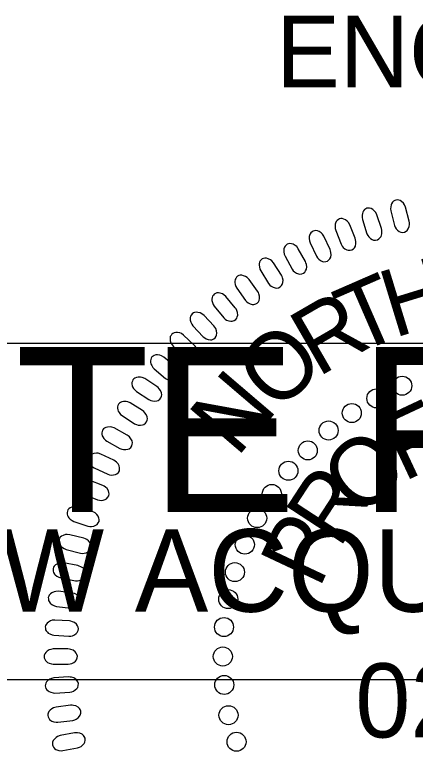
# Model space of a CAD drawing. Extents: x 1487909 to 1489267, y 497866 to 499814.
# Drawn here: x 1489041.55 to 1489044.35, y 498085.53 to 498090.67 of the extents above; entities that cross this region are included whole.
import ezdxf

# ---------------------------------------------------------------- set-up
doc = ezdxf.new("R2010")
doc.units = 0
for name, color, linetype in [('Old_Level_9', 7, 'Continuous'), ('Sheet Sticker Incomplete CELL', 7, 'Continuous'), ('Sheet Typical CELL', 7, 'Continuous')]:
    doc.layers.add(name, color=color, linetype=linetype)

msp = doc.modelspace()

# ---------------------------------------------------------------- linework, layer by layer
at = {"layer": 'Old_Level_9'}
for points in [[(1489044.308, 498089.2251), (1489044.2827, 498089.3237), (1489044.2752, 498089.3406), (1489044.2681, 498089.3508), (1489044.2556, 498089.362), (1489044.2455, 498089.3688), (1489044.2349, 498089.373), (1489044.2256, 498089.3741), (1489044.2162, 498089.3733), (1489044.2076, 498089.3694), (1489044.1986, 498089.3645), (1489044.1914, 498089.3576), (1489044.1851, 498089.3474), (1489044.1819, 498089.3398), (1489044.1795, 498089.3263), (1489044.1785, 498089.3107), (1489044.1799, 498089.2974), (1489044.2052, 498089.1962), (1489044.2105, 498089.183), (1489044.217, 498089.1727), (1489044.2275, 498089.1617), (1489044.2394, 498089.1528), (1489044.2489, 498089.1484), (1489044.2628, 498089.1468), (1489044.2752, 498089.1483), (1489044.2864, 498089.1546), (1489044.2938, 498089.1607), (1489044.3019, 498089.1714), (1489044.308, 498089.1875), (1489044.3097, 498089.2033), (1489044.3095, 498089.2143)], [(1489044.1143, 498089.1736), (1489044.0829, 498089.2704), (1489044.0743, 498089.2868), (1489044.0666, 498089.2964), (1489044.0534, 498089.307), (1489044.0429, 498089.3132), (1489044.0321, 498089.3166), (1489044.0227, 498089.3171), (1489044.0134, 498089.3157), (1489044.005, 498089.3113), (1489043.9964, 498089.3059), (1489043.9897, 498089.2985), (1489043.9839, 498089.2879), (1489043.9813, 498089.2801), (1489043.9798, 498089.2665), (1489043.9797, 498089.2508), (1489043.982, 498089.2376), (1489044.0136, 498089.1383), (1489044.0197, 498089.1255), (1489044.0268, 498089.1156), (1489044.038, 498089.1053), (1489044.0504, 498089.0971), (1489044.0601, 498089.0933), (1489044.0741, 498089.0926), (1489044.0864, 498089.0949), (1489044.0972, 498089.1019), (1489044.1042, 498089.1085), (1489044.1116, 498089.1196), (1489044.1167, 498089.1361), (1489044.1174, 498089.152), (1489044.1165, 498089.163)], [(1489043.9317, 498089.1058), (1489043.8942, 498089.2005), (1489043.8846, 498089.2163), (1489043.8763, 498089.2255), (1489043.8625, 498089.2351), (1489043.8516, 498089.2406), (1489043.8406, 498089.2433), (1489043.8313, 498089.2432), (1489043.822, 498089.2413), (1489043.8139, 498089.2364), (1489043.8056, 498089.2304), (1489043.7994, 498089.2226), (1489043.7943, 498089.2117), (1489043.7922, 498089.2038), (1489043.7915, 498089.1901), (1489043.7924, 498089.1745), (1489043.7955, 498089.1615), (1489043.8333, 498089.0642), (1489043.8402, 498089.0519), (1489043.848, 498089.0425), (1489043.8598, 498089.0328), (1489043.8726, 498089.0255), (1489043.8826, 498089.0223), (1489043.8966, 498089.0225), (1489043.9087, 498089.0255), (1489043.919, 498089.0332), (1489043.9255, 498089.0402), (1489043.9323, 498089.0518), (1489043.9364, 498089.0685), (1489043.9361, 498089.0845), (1489043.9345, 498089.0954)], [(1489043.7559, 498089.0284), (1489043.7126, 498089.1205), (1489043.702, 498089.1356), (1489043.6931, 498089.1443), (1489043.6788, 498089.1532), (1489043.6676, 498089.1579), (1489043.6563, 498089.1599), (1489043.6471, 498089.1592), (1489043.6379, 498089.1568), (1489043.6302, 498089.1513), (1489043.6223, 498089.1449), (1489043.6166, 498089.1367), (1489043.6122, 498089.1255), (1489043.6105, 498089.1174), (1489043.6108, 498089.1038), (1489043.6126, 498089.0882), (1489043.6166, 498089.0754), (1489043.6604, 498088.9808), (1489043.668, 498088.9688), (1489043.6764, 498088.9599), (1489043.6887, 498088.9511), (1489043.7021, 498088.9445), (1489043.7122, 498088.942), (1489043.7261, 498088.9431), (1489043.738, 498088.9468), (1489043.7478, 498088.9551), (1489043.754, 498088.9625), (1489043.76, 498088.9745), (1489043.763, 498088.9914), (1489043.7617, 498089.0073), (1489043.7594, 498089.0181)], [(1489043.583, 498088.9442), (1489043.534, 498089.0335), (1489043.5225, 498089.048), (1489043.5131, 498089.056), (1489043.4982, 498089.0639), (1489043.4867, 498089.068), (1489043.4754, 498089.0693), (1489043.4662, 498089.068), (1489043.4572, 498089.065), (1489043.4499, 498089.0591), (1489043.4423, 498089.0521), (1489043.4371, 498089.0436), (1489043.4335, 498089.0321), (1489043.4324, 498089.0239), (1489043.4334, 498089.0104), (1489043.4362, 498088.9949), (1489043.441, 498088.9824), (1489043.4907, 498088.8907), (1489043.499, 498088.8793), (1489043.5079, 498088.8709), (1489043.5208, 498088.8629), (1489043.5346, 498088.8572), (1489043.5448, 498088.8553), (1489043.5586, 498088.8572), (1489043.5703, 498088.8617), (1489043.5796, 498088.8706), (1489043.5852, 498088.8784), (1489043.5905, 498088.8907), (1489043.5924, 498088.9078), (1489043.5901, 498088.9236), (1489043.5871, 498088.9342)], [(1489043.4156, 498088.8494), (1489043.361, 498088.9354), (1489043.3486, 498088.9492), (1489043.3388, 498088.9566), (1489043.3234, 498088.9636), (1489043.3117, 498088.9669), (1489043.3003, 498088.9675), (1489043.2912, 498088.9656), (1489043.2825, 498088.962), (1489043.2754, 498088.9557), (1489043.2684, 498088.9483), (1489043.2637, 498088.9394), (1489043.2608, 498088.9278), (1489043.2602, 498088.9195), (1489043.2621, 498088.906), (1489043.266, 498088.8908), (1489043.2714, 498088.8786), (1489043.3268, 498088.7902), (1489043.3359, 498088.7793), (1489043.3453, 498088.7715), (1489043.3586, 498088.7643), (1489043.3727, 498088.7595), (1489043.383, 498088.7582), (1489043.3967, 498088.761), (1489043.4081, 498088.7663), (1489043.4168, 498088.7757), (1489043.4219, 498088.7839), (1489043.4264, 498088.7965), (1489043.4272, 498088.8137), (1489043.4239, 498088.8293), (1489043.4203, 498088.8397)], [(1489043.2495, 498088.737), (1489043.1897, 498088.8194), (1489043.1765, 498088.8323), (1489043.1662, 498088.8392), (1489043.1503, 498088.8451), (1489043.1385, 498088.8477), (1489043.1271, 498088.8476), (1489043.1181, 498088.8452), (1489043.1096, 498088.841), (1489043.103, 498088.8342), (1489043.0965, 498088.8264), (1489043.0923, 498088.8173), (1489043.0902, 498088.8055), (1489043.09, 498088.7972), (1489043.0928, 498088.7838), (1489043.0975, 498088.7689), (1489043.1038, 498088.7571), (1489043.1646, 498088.6723), (1489043.1744, 498088.662), (1489043.1842, 498088.6548), (1489043.198, 498088.6485), (1489043.2123, 498088.6446), (1489043.2228, 498088.6439), (1489043.2362, 498088.6476), (1489043.2472, 498088.6535), (1489043.2553, 498088.6635), (1489043.2599, 498088.6719), (1489043.2636, 498088.6848), (1489043.2634, 498088.7021), (1489043.2591, 498088.7174), (1489043.2548, 498088.7276)], [(1489043.0934, 498088.6217), (1489043.0285, 498088.7002), (1489043.0146, 498088.7122), (1489043.0038, 498088.7184), (1489042.9877, 498088.7233), (1489042.9757, 498088.7252), (1489042.9643, 498088.7244), (1489042.9555, 498088.7214), (1489042.9473, 498088.7167), (1489042.9411, 498088.7095), (1489042.9351, 498088.7013), (1489042.9315, 498088.6919), (1489042.9301, 498088.68), (1489042.9305, 498088.6717), (1489042.9341, 498088.6586), (1489042.9397, 498088.644), (1489042.9468, 498088.6325), (1489043.0127, 498088.5518), (1489043.0232, 498088.5421), (1489043.0334, 498088.5356), (1489043.0476, 498088.5301), (1489043.0621, 498088.5271), (1489043.0726, 498088.5271), (1489043.0858, 498088.5316), (1489043.0964, 498088.5383), (1489043.1038, 498088.5487), (1489043.1079, 498088.5574), (1489043.1108, 498088.5705), (1489043.1094, 498088.5877), (1489043.1042, 498088.6027), (1489043.0993, 498088.6126)], [(1489042.945, 498088.494), (1489042.8754, 498088.5682), (1489042.8607, 498088.5794), (1489042.8495, 498088.5849), (1489042.8331, 498088.5888), (1489042.8211, 498088.5899), (1489042.8097, 498088.5884), (1489042.8011, 498088.5848), (1489042.7932, 498088.5797), (1489042.7875, 498088.5721), (1489042.782, 498088.5634), (1489042.779, 498088.5539), (1489042.7784, 498088.5419), (1489042.7793, 498088.5337), (1489042.7837, 498088.5208), (1489042.7903, 498088.5066), (1489042.798, 498088.4957), (1489042.8689, 498088.4192), (1489042.8799, 498088.4102), (1489042.8905, 498088.4043), (1489042.905, 498088.3997), (1489042.9198, 498088.3976), (1489042.9302, 498088.3983), (1489042.9431, 498088.4036), (1489042.9533, 498088.4109), (1489042.96, 498088.4218), (1489042.9636, 498088.4308), (1489042.9656, 498088.444), (1489042.9632, 498088.461), (1489042.957, 498088.4758), (1489042.9515, 498088.4853)], [(1489042.8071, 498088.3604), (1489042.7329, 498088.4301), (1489042.7175, 498088.4403), (1489042.7061, 498088.4451), (1489042.6894, 498088.448), (1489042.6773, 498088.4483), (1489042.6661, 498088.4461), (1489042.6577, 498088.442), (1489042.6501, 498088.4364), (1489042.645, 498088.4285), (1489042.64, 498088.4195), (1489042.6377, 498088.4098), (1489042.6377, 498088.3978), (1489042.6392, 498088.3896), (1489042.6444, 498088.377), (1489042.6518, 498088.3633), (1489042.6602, 498088.3528), (1489042.7358, 498088.2809), (1489042.7473, 498088.2727), (1489042.7583, 498088.2674), (1489042.7731, 498088.2638), (1489042.7879, 498088.2627), (1489042.7982, 498088.264), (1489042.8108, 498088.2701), (1489042.8205, 498088.278), (1489042.8265, 498088.2893), (1489042.8295, 498088.2984), (1489042.8307, 498088.3118), (1489042.8272, 498088.3287), (1489042.8202, 498088.343), (1489042.8141, 498088.3521)], [(1489042.6732, 498088.2121), (1489042.5948, 498088.277), (1489042.5787, 498088.2862), (1489042.5671, 498088.2903), (1489042.5503, 498088.2921), (1489042.5381, 498088.2917), (1489042.5271, 498088.2887), (1489042.519, 498088.2842), (1489042.5118, 498088.278), (1489042.5071, 498088.2698), (1489042.5027, 498088.2606), (1489042.501, 498088.2508), (1489042.5018, 498088.2388), (1489042.5038, 498088.2307), (1489042.5098, 498088.2185), (1489042.5181, 498088.2051), (1489042.5271, 498088.1953), (1489042.607, 498088.1283), (1489042.6191, 498088.1208), (1489042.6304, 498088.1163), (1489042.6453, 498088.1135), (1489042.6601, 498088.1133), (1489042.6704, 498088.1154), (1489042.6826, 498088.1222), (1489042.6917, 498088.1307), (1489042.6971, 498088.1424), (1489042.6994, 498088.1517), (1489042.6998, 498088.1651), (1489042.6953, 498088.1817), (1489042.6874, 498088.1955), (1489042.6806, 498088.2043)], [(1489042.5466, 498088.0708), (1489042.4611, 498088.1261), (1489042.4441, 498088.1333), (1489042.4321, 498088.136), (1489042.4152, 498088.1358), (1489042.4032, 498088.134), (1489042.3926, 498088.1298), (1489042.3851, 498088.1243), (1489042.3786, 498088.1173), (1489042.3749, 498088.1086), (1489042.3717, 498088.0989), (1489042.3711, 498088.089), (1489042.3733, 498088.0772), (1489042.3762, 498088.0694), (1489042.3836, 498088.058), (1489042.3934, 498088.0457), (1489042.4035, 498088.037), (1489042.4908, 498087.9798), (1489042.5036, 498087.9737), (1489042.5154, 498087.9706), (1489042.5306, 498087.9697), (1489042.5453, 498087.9712), (1489042.5553, 498087.9744), (1489042.5665, 498087.9826), (1489042.5746, 498087.9921), (1489042.5786, 498088.0044), (1489042.5798, 498088.0139), (1489042.5786, 498088.0273), (1489042.5722, 498088.0432), (1489042.5627, 498088.056), (1489042.555, 498088.0639)], [(1489042.4458, 498087.9029), (1489042.3599, 498087.9575), (1489042.3429, 498087.9646), (1489042.3308, 498087.9672), (1489042.3139, 498087.9669), (1489042.3019, 498087.965), (1489042.2913, 498087.9607), (1489042.2838, 498087.9551), (1489042.2774, 498087.9481), (1489042.2739, 498087.9394), (1489042.2707, 498087.9297), (1489042.2702, 498087.9197), (1489042.2725, 498087.9079), (1489042.2754, 498087.9002), (1489042.2829, 498087.8888), (1489042.2928, 498087.8766), (1489042.303, 498087.868), (1489042.3907, 498087.8115), (1489042.4036, 498087.8056), (1489042.4154, 498087.8025), (1489042.4305, 498087.8017), (1489042.4453, 498087.8033), (1489042.4552, 498087.8065), (1489042.4664, 498087.8149), (1489042.4745, 498087.8245), (1489042.4783, 498087.8367), (1489042.4795, 498087.8463), (1489042.4782, 498087.8597), (1489042.4716, 498087.8755), (1489042.462, 498087.8882), (1489042.4543, 498087.8961)], [(1489042.3377, 498087.7328), (1489042.2484, 498087.7819), (1489042.231, 498087.788), (1489042.2187, 498087.7898), (1489042.2019, 498087.7884), (1489042.19, 498087.7857), (1489042.1798, 498087.7808), (1489042.1727, 498087.7748), (1489042.1667, 498087.7674), (1489042.1637, 498087.7584), (1489042.1611, 498087.7486), (1489042.1612, 498087.7386), (1489042.1643, 498087.727), (1489042.1677, 498087.7194), (1489042.1759, 498087.7085), (1489042.1866, 498087.697), (1489042.1973, 498087.689), (1489042.2884, 498087.6382), (1489042.3016, 498087.633), (1489042.3135, 498087.6307), (1489042.3287, 498087.6308), (1489042.3434, 498087.6334), (1489042.3531, 498087.6373), (1489042.3637, 498087.6463), (1489042.3711, 498087.6564), (1489042.3742, 498087.6688), (1489042.3748, 498087.6784), (1489042.3726, 498087.6917), (1489042.3651, 498087.7071), (1489042.3547, 498087.7192), (1489042.3465, 498087.7266)], [(1489042.2456, 498087.5566), (1489042.1535, 498087.5999), (1489042.1357, 498087.6049), (1489042.1234, 498087.6059), (1489042.1067, 498087.6035), (1489042.095, 498087.6001), (1489042.0851, 498087.5945), (1489042.0783, 498087.588), (1489042.0729, 498087.5803), (1489042.0704, 498087.5712), (1489042.0685, 498087.5611), (1489042.0692, 498087.5512), (1489042.073, 498087.5398), (1489042.0769, 498087.5325), (1489042.0858, 498087.5221), (1489042.0971, 498087.5113), (1489042.1083, 498087.5039), (1489042.2025, 498087.4589), (1489042.2159, 498087.4547), (1489042.228, 498087.4531), (1489042.2431, 498087.4542), (1489042.2576, 498087.4577), (1489042.267, 498087.4621), (1489042.2771, 498087.4718), (1489042.2839, 498087.4823), (1489042.2861, 498087.495), (1489042.2861, 498087.5046), (1489042.2831, 498087.5177), (1489042.2746, 498087.5327), (1489042.2635, 498087.544), (1489042.2548, 498087.5509)], [(1489042.1677, 498087.3807), (1489042.073, 498087.4182), (1489042.0549, 498087.422), (1489042.0426, 498087.4223), (1489042.026, 498087.4188), (1489042.0146, 498087.4147), (1489042.005, 498087.4084), (1489041.9988, 498087.4016), (1489041.9938, 498087.3935), (1489041.9919, 498087.3843), (1489041.9906, 498087.3741), (1489041.9919, 498087.3642), (1489041.9964, 498087.3531), (1489042.0008, 498087.346), (1489042.0103, 498087.3363), (1489042.0223, 498087.3262), (1489042.0339, 498087.3196), (1489042.1306, 498087.2806), (1489042.1444, 498087.2772), (1489042.1566, 498087.2763), (1489042.1716, 498087.2783), (1489042.1858, 498087.2827), (1489042.1949, 498087.2878), (1489042.2044, 498087.2981), (1489042.2105, 498087.309), (1489042.212, 498087.3217), (1489042.2113, 498087.3314), (1489042.2075, 498087.3442), (1489042.1981, 498087.3586), (1489042.1862, 498087.3693), (1489042.1771, 498087.3756)], [(1489042.095, 498087.199), (1489041.9981, 498087.2305), (1489041.9799, 498087.2331), (1489041.9675, 498087.2327), (1489041.9512, 498087.2282), (1489041.94, 498087.2233), (1489041.9309, 498087.2165), (1489041.9251, 498087.2093), (1489041.9206, 498087.2009), (1489041.9193, 498087.1915), (1489041.9186, 498087.1813), (1489041.9206, 498087.1716), (1489041.9258, 498087.1607), (1489041.9306, 498087.1539), (1489041.9407, 498087.1448), (1489041.9533, 498087.1355), (1489041.9653, 498087.1296), (1489042.0643, 498087.0967), (1489042.0783, 498087.0942), (1489042.0905, 498087.0941), (1489042.1053, 498087.0971), (1489042.1192, 498087.1024), (1489042.1281, 498087.108), (1489042.1368, 498087.1188), (1489042.1422, 498087.1301), (1489042.1429, 498087.143), (1489042.1416, 498087.1525), (1489042.1371, 498087.1651), (1489042.1267, 498087.1789), (1489042.1143, 498087.1888), (1489042.1048, 498087.1945)], [(1489042.0365, 498087.0118), (1489041.9379, 498087.0371), (1489041.9195, 498087.0386), (1489041.9071, 498087.0374), (1489041.8912, 498087.0318), (1489041.8804, 498087.0263), (1489041.8716, 498087.019), (1489041.8663, 498087.0113), (1489041.8623, 498087.0027), (1489041.8616, 498086.9934), (1489041.8616, 498086.9831), (1489041.8642, 498086.9734), (1489041.8701, 498086.963), (1489041.8752, 498086.9565), (1489041.8859, 498086.948), (1489041.8991, 498086.9395), (1489041.9114, 498086.9344), (1489042.0123, 498086.9078), (1489042.0264, 498086.9061), (1489042.0386, 498086.9068), (1489042.0532, 498086.9108), (1489042.0667, 498086.9169), (1489042.0752, 498086.923), (1489042.0833, 498086.9344), (1489042.0879, 498086.946), (1489042.0878, 498086.9588), (1489042.086, 498086.9683), (1489042.0806, 498086.9806), (1489042.0695, 498086.9937), (1489042.0564, 498087.0028), (1489042.0466, 498087.0079)], [(1489041.9941, 498086.8212), (1489041.8941, 498086.8403), (1489041.8756, 498086.8407), (1489041.8634, 498086.8387), (1489041.8478, 498086.8321), (1489041.8373, 498086.826), (1489041.8291, 498086.818), (1489041.8242, 498086.8101), (1489041.8208, 498086.8013), (1489041.8208, 498086.7919), (1489041.8213, 498086.7816), (1489041.8245, 498086.7722), (1489041.8311, 498086.7621), (1489041.8366, 498086.756), (1489041.8478, 498086.7481), (1489041.8615, 498086.7405), (1489041.8741, 498086.7362), (1489041.9765, 498086.7159), (1489041.9907, 498086.7152), (1489042.0027, 498086.7167), (1489042.0171, 498086.7215), (1489042.0303, 498086.7284), (1489042.0383, 498086.7351), (1489042.0456, 498086.747), (1489042.0496, 498086.7589), (1489042.0486, 498086.7717), (1489042.0462, 498086.781), (1489042.0401, 498086.7929), (1489042.0281, 498086.8053), (1489042.0145, 498086.8136), (1489042.0044, 498086.818)], [(1489041.9592, 498086.6291), (1489041.8582, 498086.6419), (1489041.8397, 498086.6412), (1489041.8276, 498086.6383), (1489041.8125, 498086.6309), (1489041.8025, 498086.624), (1489041.7947, 498086.6156), (1489041.7904, 498086.6074), (1489041.7875, 498086.5983), (1489041.788, 498086.5889), (1489041.7893, 498086.5787), (1489041.7931, 498086.5695), (1489041.8002, 498086.5599), (1489041.8062, 498086.5541), (1489041.8178, 498086.547), (1489041.8319, 498086.5402), (1489041.8448, 498086.5367), (1489041.9482, 498086.523), (1489041.9624, 498086.5231), (1489041.9744, 498086.5253), (1489041.9884, 498086.531), (1489042.0011, 498086.5388), (1489042.0087, 498086.546), (1489042.0153, 498086.5583), (1489042.0185, 498086.5704), (1489042.0167, 498086.5831), (1489042.0137, 498086.5923), (1489042.0069, 498086.6038), (1489041.9941, 498086.6153), (1489041.98, 498086.6228), (1489041.9697, 498086.6266)], [(1489041.9354, 498086.4346), (1489041.8338, 498086.441), (1489041.8154, 498086.4391), (1489041.8035, 498086.4355), (1489041.7889, 498086.4271), (1489041.7793, 498086.4196), (1489041.7721, 498086.4108), (1489041.7683, 498086.4023), (1489041.766, 498086.3931), (1489041.7671, 498086.3837), (1489041.769, 498086.3736), (1489041.7733, 498086.3647), (1489041.7811, 498086.3555), (1489041.7874, 498086.3501), (1489041.7994, 498086.3437), (1489041.814, 498086.3378), (1489041.8271, 498086.3352), (1489041.9311, 498086.3279), (1489041.9453, 498086.3289), (1489041.9571, 498086.3319), (1489041.9708, 498086.3385), (1489041.9829, 498086.347), (1489041.9901, 498086.3547), (1489041.9958, 498086.3674), (1489041.9982, 498086.3797), (1489041.9957, 498086.3922), (1489041.9921, 498086.4012), (1489041.9846, 498086.4122), (1489041.9712, 498086.423), (1489041.9566, 498086.4296), (1489041.946, 498086.4327)], [(1489041.9246, 498086.2395), (1489041.8228, 498086.2395), (1489041.8046, 498086.2364), (1489041.793, 498086.2321), (1489041.7789, 498086.2228), (1489041.7698, 498086.2147), (1489041.7632, 498086.2054), (1489041.7599, 498086.1967), (1489041.7582, 498086.1874), (1489041.7599, 498086.1781), (1489041.7623, 498086.1682), (1489041.7673, 498086.1595), (1489041.7756, 498086.1508), (1489041.7822, 498086.1458), (1489041.7946, 498086.1402), (1489041.8095, 498086.1353), (1489041.8227, 498086.1334), (1489041.9271, 498086.1328), (1489041.9411, 498086.1346), (1489041.9527, 498086.1384), (1489041.9659, 498086.1458), (1489041.9775, 498086.1551), (1489041.9842, 498086.1632), (1489041.9892, 498086.1762), (1489041.9908, 498086.1886), (1489041.9875, 498086.201), (1489041.9833, 498086.2097), (1489041.9751, 498086.2203), (1489041.961, 498086.2302), (1489041.9461, 498086.2358), (1489041.9353, 498086.2382)], [(1489041.929, 498086.0438), (1489041.8273, 498086.0375), (1489041.8094, 498086.0332), (1489041.798, 498086.0282), (1489041.7846, 498086.018), (1489041.7759, 498086.0094), (1489041.7699, 498085.9997), (1489041.7672, 498085.9908), (1489041.7662, 498085.9814), (1489041.7684, 498085.9723), (1489041.7715, 498085.9625), (1489041.7769, 498085.9541), (1489041.7858, 498085.946), (1489041.7927, 498085.9414), (1489041.8054, 498085.9366), (1489041.8206, 498085.9326), (1489041.8339, 498085.9316), (1489041.9381, 498085.9375), (1489041.952, 498085.9402), (1489041.9633, 498085.9447), (1489041.9761, 498085.9529), (1489041.9871, 498085.9629), (1489041.9932, 498085.9713), (1489041.9974, 498085.9847), (1489041.9982, 498085.9972), (1489041.9941, 498086.0094), (1489041.9895, 498086.0178), (1489041.9805, 498086.0278), (1489041.9659, 498086.0368), (1489041.9506, 498086.0414), (1489041.9397, 498086.0433)], [(1489041.9426, 498085.8462), (1489041.8416, 498085.8335), (1489041.8239, 498085.8281), (1489041.8129, 498085.8224), (1489041.8002, 498085.8113), (1489041.7921, 498085.8022), (1489041.7867, 498085.7921), (1489041.7846, 498085.7831), (1489041.7841, 498085.7736), (1489041.7869, 498085.7647), (1489041.7906, 498085.7551), (1489041.7965, 498085.7471), (1489041.8059, 498085.7395), (1489041.8131, 498085.7354), (1489041.8261, 498085.7314), (1489041.8415, 498085.7284), (1489041.8549, 498085.7282), (1489041.9584, 498085.7406), (1489041.9721, 498085.7442), (1489041.9832, 498085.7494), (1489041.9954, 498085.7584), (1489042.0057, 498085.769), (1489042.0113, 498085.7779), (1489042.0146, 498085.7914), (1489042.0147, 498085.804), (1489042.0098, 498085.8159), (1489042.0046, 498085.824), (1489041.9951, 498085.8334), (1489041.9799, 498085.8415), (1489041.9644, 498085.8451), (1489041.9534, 498085.8463)], [(1489041.9703, 498085.6532), (1489041.8703, 498085.6341), (1489041.8529, 498085.6277), (1489041.8424, 498085.6213), (1489041.8303, 498085.6094), (1489041.8228, 498085.5998), (1489041.8181, 498085.5894), (1489041.8165, 498085.5803), (1489041.8166, 498085.5708), (1489041.82, 498085.562), (1489041.8243, 498085.5528), (1489041.8307, 498085.5451), (1489041.8405, 498085.5382), (1489041.8479, 498085.5345), (1489041.8612, 498085.5313), (1489041.8768, 498085.5292), (1489041.8901, 498085.5299), (1489041.9927, 498085.5488), (1489042.0061, 498085.5533), (1489042.0169, 498085.5591), (1489042.0284, 498085.5689), (1489042.0381, 498085.5802), (1489042.0431, 498085.5894), (1489042.0455, 498085.6031), (1489042.0448, 498085.6156), (1489042.0393, 498085.6271), (1489042.0336, 498085.6349), (1489042.0235, 498085.6437), (1489042.0078, 498085.6508), (1489041.9921, 498085.6535), (1489041.9811, 498085.6539)]]:
    msp.add_lwpolyline(points, close=True, dxfattribs=at)
for centre in [(1489044.2599, 498088.0768), (1489044.0794, 498087.9888), (1489043.9076, 498087.8863), (1489043.7456, 498087.7641), (1489043.6002, 498087.6252), (1489043.4646, 498087.4831), (1489043.3489, 498087.3211), (1489043.2464, 498087.1525), (1489043.1605, 498086.9674), (1489043.091, 498086.7756), (1489043.0447, 498086.5872), (1489043.0149, 498086.3921), (1489043.0068, 498086.1867), (1489043.0167, 498085.9883), (1489043.0464, 498085.7767), (1489043.1025, 498085.5915)]:
    msp.add_circle(centre, 0.0665, dxfattribs=at)
at = {"layer": 'Sheet Sticker Incomplete CELL'}
msp.add_lwpolyline([(1489032.6136, 498086.0242), (1489032.6136, 498088.3742), (1489047.3136, 498088.3742), (1489047.3136, 498086.0242)], close=True, dxfattribs=at)

# ---------------------------------------------------------------- texts
at = {"layer": 'Old_Level_9'}
for s, height, rotation, p in [('H', 0.4706, 17.0557, (1489044.2009, 498088.4086)), ('T', 0.4706, 23.5451, (1489043.9371, 498088.2916)), ('R', 0.4706, 30.0345, (1489043.6697, 498088.1323)), ('O', 0.4706, 43.0132, (1489043.3813, 498087.881)), ('N', 0.4706, 49.5025, (1489043.1035, 498087.5693)), ('F', 0.4706, 25.1084, (1489044.2678, 498087.4037)), ('O', 0.4706, 40.988, (1489043.961, 498087.1432)), ('R', 0.4706, 56.8676, (1489043.8187, 498086.9318)), ('P', 0.4706, 64.8074, (1489043.6787, 498086.6528)), ('024964', 0.51761, 359.9814, (1489043.9318, 498085.6214))]:
    msp.add_text(s, height=height, rotation=rotation, dxfattribs=at).set_placement(p)
at = {"layer": 'Sheet Sticker Incomplete CELL'}
for s, height, p in [('INCOMPLETE PLANS', 1.152, (1489033.5086, 498087.1942)), ('DO NOT USE FOR R/W ACQUISITION', 0.576, (1489033.8336, 498086.4992))]:
    msp.add_text(s, height=height, dxfattribs=at).set_placement(p)
at = {"layer": 'Sheet Typical CELL'}
msp.add_text('ENGINEER', height=0.50001, dxfattribs=at).set_placement((1489043.3786, 498090.1592))

doc.saveas('drawing.dxf')
